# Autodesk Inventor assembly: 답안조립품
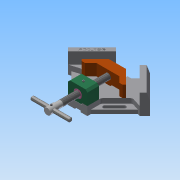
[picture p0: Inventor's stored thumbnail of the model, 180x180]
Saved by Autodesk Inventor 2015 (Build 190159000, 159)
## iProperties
Created: 2020-05
Part Number: 답안조립품
Document SubType Name: Assembly
Designer: 105687
Author: 105687
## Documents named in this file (11)
- C:\Users\105687\Desktop\700506V1053\답안조립품.iam
- C:\Users\105687\Desktop\700506V1053\본체.ipt
- C:\Users\105687\Desktop\700506V1053\리드스크류.ipt
- C:\Users\105687\Desktop\700506V1053\멈춤나사 M4x5.ipt
- C:\Users\105687\Desktop\700506V1053\멈춤나사 M4x10.ipt
- C:\Users\105687\Desktop\700506V1053\볼트 M4x16.ipt
- C:\Users\105687\Desktop\700506V1053\부시.ipt
- C:\Users\105687\Desktop\700506V1053\서포트.ipt
- C:\Users\105687\Desktop\700506V1053\조.ipt
- C:\Users\105687\Desktop\700506V1053\평행 핀 2.5x24.ipt
- C:\Users\105687\Desktop\700506V1053\핸들.ipt
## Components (1 placed, 1 different names)
1. 핸들:1
